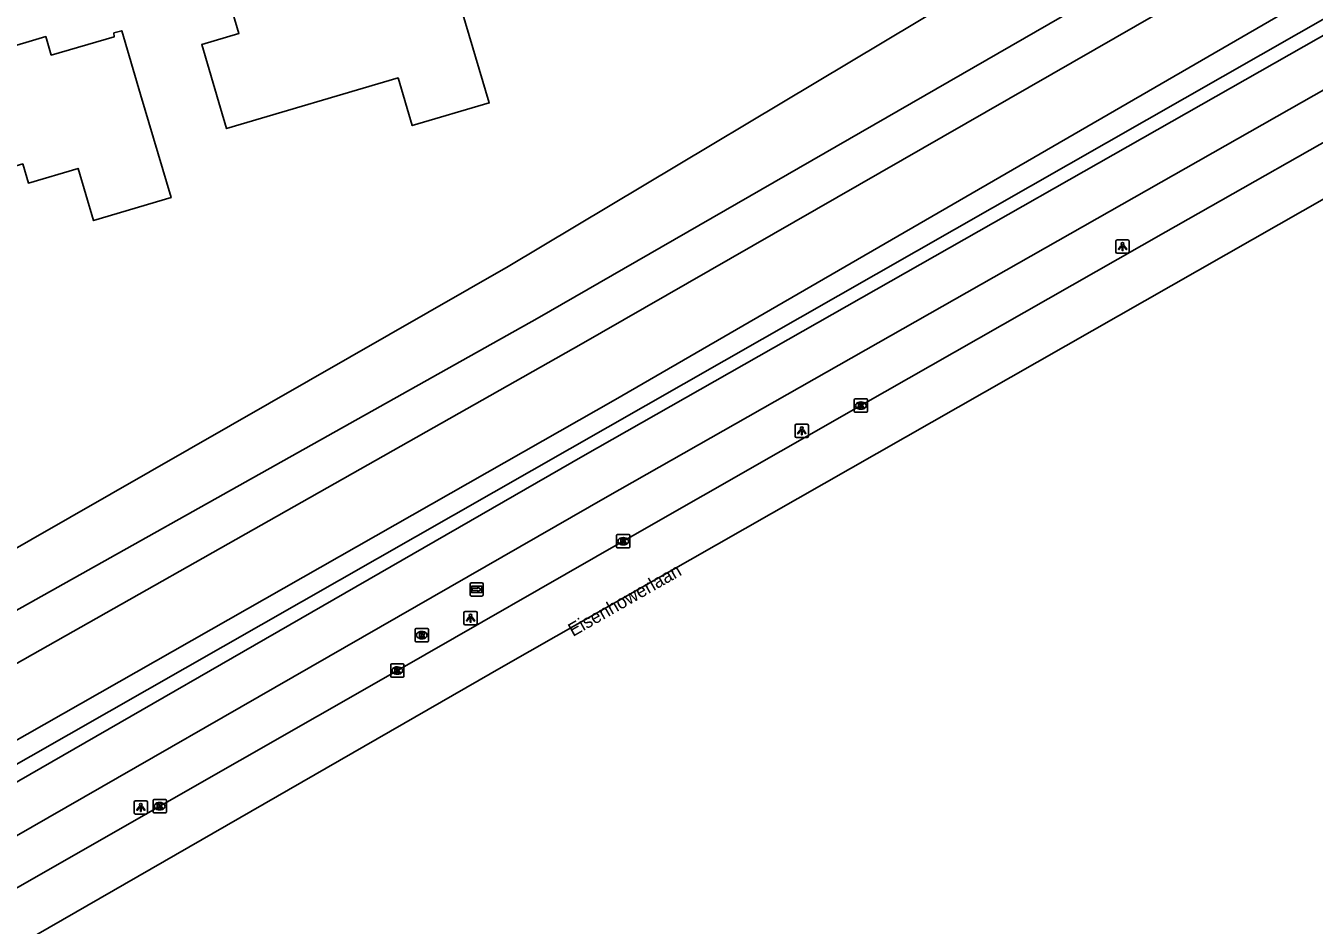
# Model space of a CAD drawing. Extents: x 162417 to 163721, y 384268 to 385416.
# Drawn here: x 163373.9 to 163470.9, y 384526.5 to 384594.2 of the extents above; entities that cross this region are included whole.
import ezdxf

# ---------------------------------------------------------------- set-up
doc = ezdxf.new("R2010")
doc.units = 0
for name, color, linetype in [('IMGEO_Fietspad_gesloten', 7, 'Continuous'), ('IMGEO_Groenvoorziening', 7, 'Continuous'), ('IMGEO_Hek', 7, 'Continuous'), ('IMGEO_Kolk', 7, 'Continuous'), ('IMGEO_Lichtpunt', 7, 'Continuous'), ('IMGEO_Openbare_ruimte_label', 7, 'Continuous'), ('IMGEO_Pand', 7, 'Continuous'), ('IMGEO_Rijbaan_regionaal_gesloten', 7, 'Continuous'), ('IMGEO_Rioolput', 7, 'Continuous'), ('IMGEO_Wegwijzer', 7, 'Continuous')]:
    doc.layers.add(name, color=color, linetype=linetype)

msp = doc.modelspace()

# ---------------------------------------------------------------- linework, layer by layer
at = {"layer": 'IMGEO_Fietspad_gesloten'}
for points in [[(163563.615, 384641.938), (163546.208, 384631.66), (163524.745, 384619.501), (163513.726, 384613.258), (163500, 384605.489), (163486.444, 384597.816), (163417.722, 384558.756), (163354.577, 384522.522), (163336.983, 384512.304), (163315.799, 384500), (163237.627, 384454.426), (163127.281, 384389.626), (163118.59, 384384.62), (163112.281, 384381.199), (163106.553, 384378.4)], [(163511.147, 384615.916), (163500, 384609.604), (163484.5, 384600.835), (163415.868, 384561.799), (163356.283, 384527.511), (163355.13, 384526.85)]]:
    msp.add_lwpolyline(points, dxfattribs=at)
at = {"layer": 'IMGEO_Groenvoorziening'}
for points in [[(163490.386, 384642.261), (163488.848, 384640.395), (163492.655, 384633.034), (163494.178, 384625.448), (163477.053, 384616.061), (163410.245, 384576.085), (163356.302, 384545.212), (163353.612, 384549.684), (163345.242, 384548.875)], [(163497.843, 384621.571), (163489.45, 384616.524), (163412.421, 384572.167), (163356.605, 384540.896), (163352.187, 384546.648), (163350.391, 384546.23), (163353.961, 384535.291), (163415.728, 384570.225), (163496.132, 384616.406), (163500, 384619.404), (163501.9, 384620.876)], [(163508.242, 384618.879), (163507.381, 384617.632), (163500, 384613.359), (163418.315, 384566.067), (163354.498, 384529.757)], [(163510.332, 384616.812), (163354.09, 384527.692), (163351.378, 384528.626), (163350.849, 384530.373)]]:
    msp.add_lwpolyline(points, dxfattribs=at)
at = {"layer": 'IMGEO_Hek'}
msp.add_lwpolyline([(163510.332, 384616.812), (163354.09, 384527.692), (163351.378, 384528.626), (163350.849, 384530.373)], dxfattribs=at)
at = {"layer": 'IMGEO_Kolk'}
for p, q in [((163436.298, 384565.181), (163436.298, 384566.033)), ((163436.373, 384566.107), (163437.225, 384566.107)), ((163436.786, 384565.887), (163436.811, 384565.887)), ((163437.299, 384566.033), (163437.299, 384565.181)), ((163437.225, 384565.107), (163436.373, 384565.107)), ((163436.809, 384565.327), (163436.784, 384565.327)), ((163418.404, 384554.965), (163418.404, 384555.817)), ((163418.479, 384555.891), (163419.331, 384555.891)), ((163418.892, 384555.671), (163418.917, 384555.671)), ((163419.405, 384555.817), (163419.405, 384554.965)), ((163419.331, 384554.891), (163418.479, 384554.891)), ((163418.915, 384555.111), (163418.89, 384555.111)), ((163401.395, 384545.226), (163401.395, 384546.078)), ((163401.47, 384546.152), (163402.322, 384546.152)), ((163401.883, 384545.932), (163401.908, 384545.932)), ((163402.396, 384546.078), (163402.396, 384545.226)), ((163402.322, 384545.152), (163401.47, 384545.152)), ((163401.906, 384545.372), (163401.881, 384545.372)), ((163383.505, 384535.012), (163383.505, 384535.864)), ((163383.58, 384535.938), (163384.432, 384535.938)), ((163384.506, 384535.864), (163384.506, 384535.012)), ((163384.432, 384534.938), (163383.58, 384534.938)), ((163384.016, 384535.158), (163383.991, 384535.158)), ((163383.993, 384535.718), (163384.018, 384535.718))]:
    msp.add_line(p, q, dxfattribs=at)
for points in [[(163436.298, 384565.181), (163436.298, 384566.033)], [(163436.373, 384566.107), (163437.225, 384566.107)], [(163436.619, 384565.807), (163436.742, 384565.807), (163436.742, 384565.656), (163436.872, 384565.807), (163437.036, 384565.807), (163436.89, 384565.656), (163437.043, 384565.407), (163436.891, 384565.407), (163436.806, 384565.571), (163436.742, 384565.504), (163436.742, 384565.407), (163436.619, 384565.407), (163436.619, 384565.807)], [(163437.299, 384566.033), (163437.299, 384565.181)], [(163437.225, 384565.107), (163436.373, 384565.107)], [(163418.404, 384554.965), (163418.404, 384555.817)], [(163418.479, 384555.891), (163419.331, 384555.891)], [(163418.725, 384555.591), (163418.848, 384555.591), (163418.848, 384555.44), (163418.978, 384555.591), (163419.142, 384555.591), (163418.996, 384555.44), (163419.149, 384555.191), (163418.997, 384555.191), (163418.912, 384555.355), (163418.848, 384555.288), (163418.848, 384555.191), (163418.725, 384555.191), (163418.725, 384555.591)], [(163419.405, 384555.817), (163419.405, 384554.965)], [(163419.331, 384554.891), (163418.479, 384554.891)], [(163401.395, 384545.226), (163401.395, 384546.078)], [(163401.47, 384546.152), (163402.322, 384546.152)], [(163401.716, 384545.852), (163401.839, 384545.852), (163401.839, 384545.701), (163401.969, 384545.852), (163402.133, 384545.852), (163401.987, 384545.701), (163402.14, 384545.452), (163401.988, 384545.452), (163401.903, 384545.616), (163401.839, 384545.549), (163401.839, 384545.452), (163401.716, 384545.452), (163401.716, 384545.852)], [(163402.396, 384546.078), (163402.396, 384545.226)], [(163402.322, 384545.152), (163401.47, 384545.152)], [(163383.505, 384535.012), (163383.505, 384535.864)], [(163383.58, 384535.938), (163384.432, 384535.938)], [(163384.506, 384535.864), (163384.506, 384535.012)], [(163384.432, 384534.938), (163383.58, 384534.938)], [(163383.826, 384535.638), (163383.949, 384535.638), (163383.949, 384535.487), (163384.079, 384535.638), (163384.243, 384535.638), (163384.097, 384535.487), (163384.25, 384535.238), (163384.098, 384535.238), (163384.013, 384535.402), (163383.949, 384535.335), (163383.949, 384535.238), (163383.826, 384535.238), (163383.826, 384535.638)]]:
    msp.add_lwpolyline(points, dxfattribs=at)
for centre, start, end in [((163436.375, 384566.031), 91.55205, 178.44795), ((163436.375, 384566.031), 91.55205, 178.44795), ((163437.223, 384566.031), 1.55205, 88.44795), ((163437.223, 384566.031), 1.55205, 88.44795), ((163436.375, 384565.183), 181.55205, 268.44795), ((163436.375, 384565.183), 181.55205, 268.44795), ((163437.223, 384565.183), 271.55205, 358.44795), ((163437.223, 384565.183), 271.55205, 358.44795), ((163418.481, 384555.815), 91.55205, 178.44795), ((163418.481, 384555.815), 91.55205, 178.44795), ((163419.329, 384555.815), 1.55205, 88.44795), ((163419.329, 384555.815), 1.55205, 88.44795), ((163418.481, 384554.967), 181.55205, 268.44795), ((163418.481, 384554.967), 181.55205, 268.44795), ((163419.329, 384554.967), 271.55205, 358.44795), ((163419.329, 384554.967), 271.55205, 358.44795), ((163401.472, 384546.076), 91.55205, 178.44795), ((163401.472, 384546.076), 91.55205, 178.44795), ((163402.32, 384546.076), 1.55205, 88.44795), ((163402.32, 384546.076), 1.55205, 88.44795), ((163401.472, 384545.228), 181.55205, 268.44795), ((163401.472, 384545.228), 181.55205, 268.44795), ((163402.32, 384545.228), 271.55205, 358.44795), ((163402.32, 384545.228), 271.55205, 358.44795), ((163383.582, 384535.862), 91.55205, 178.44795), ((163383.582, 384535.862), 91.55205, 178.44795), ((163384.43, 384535.862), 1.55205, 88.44795), ((163384.43, 384535.862), 1.55205, 88.44795), ((163383.582, 384535.014), 181.55205, 268.44795), ((163383.582, 384535.014), 181.55205, 268.44795), ((163384.43, 384535.014), 271.55205, 358.44795), ((163384.43, 384535.014), 271.55205, 358.44795)]:
    msp.add_arc(centre, 0.0765, start, end, dxfattribs=at)
for centre, major_axis, ratio, start_param, end_param in [((163436.785, 384565.607), (-0.387, 0.002), 0.722429, 4.712389, 7.853982), ((163436.81, 384565.607), (-0.39, 0.002), 0.717154, 1.570796, 4.712389), ((163418.891, 384555.391), (-0.387, 0.002), 0.722429, 4.712389, 7.853982), ((163418.916, 384555.391), (-0.39, 0.002), 0.717154, 1.570796, 4.712389), ((163401.882, 384545.652), (-0.387, 0.002), 0.722429, 4.712389, 7.853982), ((163401.907, 384545.652), (-0.39, 0.002), 0.717154, 1.570796, 4.712389), ((163383.992, 384535.438), (-0.387, 0.002), 0.722429, 4.712389, 7.853982), ((163384.017, 384535.438), (-0.39, 0.002), 0.717154, 1.570796, 4.712389)]:
    msp.add_ellipse(centre, major_axis=major_axis, ratio=ratio, start_param=start_param, end_param=end_param, dxfattribs=at)
at = {"layer": 'IMGEO_Lichtpunt'}
for p, q in [((163455.994, 384577.985), (163455.994, 384577.178)), ((163455.994, 384577.985), (163455.994, 384577.178)), ((163456.896, 384578.08), (163456.088, 384578.08)), ((163456.896, 384578.08), (163456.088, 384578.08)), ((163456.99, 384577.178), (163456.99, 384577.985)), ((163456.99, 384577.178), (163456.99, 384577.985)), ((163456.088, 384577.084), (163456.896, 384577.084)), ((163456.088, 384577.084), (163456.896, 384577.084)), ((163431.841, 384564.114), (163431.841, 384563.307)), ((163431.841, 384564.114), (163431.841, 384563.307)), ((163432.743, 384564.209), (163431.935, 384564.209)), ((163432.743, 384564.209), (163431.935, 384564.209)), ((163432.837, 384563.307), (163432.837, 384564.114)), ((163432.837, 384563.307), (163432.837, 384564.114)), ((163431.935, 384563.213), (163432.743, 384563.213)), ((163431.935, 384563.213), (163432.743, 384563.213)), ((163406.912, 384550.003), (163406.912, 384549.196)), ((163406.912, 384550.003), (163406.912, 384549.196)), ((163407.814, 384550.098), (163407.006, 384550.098)), ((163407.814, 384550.098), (163407.006, 384550.098)), ((163407.908, 384549.196), (163407.908, 384550.003)), ((163407.908, 384549.196), (163407.908, 384550.003)), ((163407.006, 384549.102), (163407.814, 384549.102)), ((163407.006, 384549.102), (163407.814, 384549.102)), ((163382.085, 384535.753), (163382.085, 384534.946)), ((163382.085, 384535.753), (163382.085, 384534.946)), ((163382.987, 384535.848), (163382.179, 384535.848)), ((163382.987, 384535.848), (163382.179, 384535.848)), ((163383.081, 384534.946), (163383.081, 384535.753)), ((163383.081, 384534.946), (163383.081, 384535.753)), ((163382.179, 384534.852), (163382.987, 384534.852)), ((163382.179, 384534.852), (163382.987, 384534.852))]:
    msp.add_line(p, q, dxfattribs=at)
for points in [[(163456.368, 384577.649), (163456.407, 384577.621), (163456.219, 384577.359), (163456.181, 384577.386), (163456.368, 384577.649)], [(163456.47, 384577.601), (163456.517, 384577.601), (163456.517, 384577.279), (163456.47, 384577.279), (163456.47, 384577.601)], [(163456.58, 384577.621), (163456.618, 384577.648), (163456.805, 384577.386), (163456.766, 384577.358), (163456.58, 384577.621)], [(163432.215, 384563.778), (163432.254, 384563.75), (163432.066, 384563.488), (163432.028, 384563.515), (163432.215, 384563.778)], [(163432.317, 384563.73), (163432.364, 384563.73), (163432.364, 384563.408), (163432.317, 384563.408), (163432.317, 384563.73)], [(163432.427, 384563.75), (163432.465, 384563.777), (163432.652, 384563.515), (163432.613, 384563.487), (163432.427, 384563.75)], [(163407.286, 384549.667), (163407.325, 384549.639), (163407.137, 384549.377), (163407.099, 384549.404), (163407.286, 384549.667)], [(163407.388, 384549.619), (163407.435, 384549.619), (163407.435, 384549.297), (163407.388, 384549.297), (163407.388, 384549.619)], [(163407.498, 384549.639), (163407.536, 384549.666), (163407.723, 384549.404), (163407.684, 384549.376), (163407.498, 384549.639)], [(163382.459, 384535.417), (163382.498, 384535.389), (163382.31, 384535.127), (163382.272, 384535.154), (163382.459, 384535.417)], [(163382.561, 384535.369), (163382.608, 384535.369), (163382.608, 384535.047), (163382.561, 384535.047), (163382.561, 384535.369)], [(163382.671, 384535.389), (163382.709, 384535.416), (163382.896, 384535.154), (163382.857, 384535.126), (163382.671, 384535.389)]]:
    msp.add_lwpolyline(points, dxfattribs=at)
for centre in [(163456.493, 384577.783), (163432.34, 384563.912), (163407.411, 384549.801), (163382.584, 384535.551)]:
    msp.add_circle(centre, 0.0994, dxfattribs=at)
for centre, start, end in [((163456.088, 384577.985), 90, 180), ((163456.088, 384577.985), 90, 180), ((163456.896, 384577.985), 0, 90), ((163456.896, 384577.985), 0, 90), ((163456.088, 384577.178), 180, 270), ((163456.088, 384577.178), 180, 270), ((163456.896, 384577.178), 270, 0), ((163456.896, 384577.178), 270, 360), ((163431.935, 384564.114), 90, 180), ((163431.935, 384564.114), 90, 180), ((163432.743, 384564.114), 0, 90), ((163432.743, 384564.114), 0, 90), ((163431.935, 384563.307), 180, 270), ((163431.935, 384563.307), 180, 270), ((163432.743, 384563.307), 270, 0), ((163432.743, 384563.307), 270, 360), ((163407.006, 384550.003), 90, 180), ((163407.006, 384550.003), 90, 180), ((163407.814, 384550.003), 0, 90), ((163407.814, 384550.003), 0, 90), ((163407.006, 384549.196), 180, 270), ((163407.006, 384549.196), 180, 270), ((163407.814, 384549.196), 270, 0), ((163407.814, 384549.196), 270, 360), ((163382.179, 384535.753), 90, 180), ((163382.179, 384535.753), 90, 180), ((163382.987, 384535.753), 0, 90), ((163382.987, 384535.753), 0, 90), ((163382.179, 384534.946), 180, 270), ((163382.179, 384534.946), 180, 270), ((163382.987, 384534.946), 270, 0), ((163382.987, 384534.946), 270, 360)]:
    msp.add_arc(centre, 0.0946, start, end, dxfattribs=at)
at = {"layer": 'IMGEO_Pand'}
for points in [[(163388.86, 384597.387), (163389.971, 384593.627), (163387.17, 384592.799), (163388.587, 384588.004), (163389.04, 384586.469), (163401.957, 384590.287), (163403.019, 384586.69), (163408.811, 384588.401), (163405.052, 384601.119), (163403.635, 384605.913), (163397.853, 384604.204), (163398.987, 384600.369), (163392.697, 384598.51)], [(163365.825, 384590.479), (163364.706, 384590.192), (163360.682, 384589.023), (163362.106, 384584.231), (163363.586, 384579.248), (163364.755, 384575.318), (163371.456, 384577.31), (163370.27, 384581.226), (163369.845, 384582.664), (163373.698, 384583.805), (163374.124, 384582.367), (163377.865, 384583.474), (163379.028, 384579.543), (163384.859, 384581.269), (163382.561, 384589.036), (163381.143, 384593.83), (163380.557, 384593.672), (163380.59, 384593.387), (163375.844, 384591.998), (163375.427, 384593.399), (163368.54, 384591.356), (163369.07, 384589.543), (163367.915, 384589.188), (163367.599, 384590.132)]]:
    msp.add_lwpolyline(points, dxfattribs=at)
at = {"layer": 'IMGEO_Rijbaan_regionaal_gesloten'}
for points in [[(163698.754, 384708.845), (163688.73, 384703.305), (163649.638, 384681.228), (163618.533, 384663.566), (163596.045, 384651.581), (163528.5, 384613.585), (163468.247, 384579.241), (163409.885, 384545.975), (163340.634, 384506.16), (163340.62, 384506.152), (163245.344, 384450.732), (163192.965, 384420.029), (163150.615, 384395.072), (163132.36, 384384.338), (163123.086, 384378.886)], [(163159.702, 384404.658), (163177.428, 384415.092), (163194.296, 384425.014), (163209.47, 384433.918), (163228.943, 384445.358), (163245.842, 384455.282), (163261.887, 384464.663), (163280.528, 384475.539), (163295.714, 384484.368), (163315.265, 384495.759), (163322.552, 384500), (163332.188, 384505.608), (163338.716, 384509.388), (163350.031, 384515.939), (163367.013, 384525.722), (163384.007, 384535.437), (163401.897, 384545.651), (163418.907, 384555.39), (163436.8, 384565.606), (163459.744, 384578.685), (163476.382, 384588.124)]]:
    msp.add_lwpolyline(points, dxfattribs=at)
at = {"layer": 'IMGEO_Rioolput'}
for p, q in [((163403.237, 384547.898), (163403.237, 384548.75)), ((163403.312, 384548.824), (163404.164, 384548.824)), ((163403.725, 384548.604), (163403.75, 384548.604)), ((163404.238, 384548.75), (163404.238, 384547.898)), ((163404.164, 384547.824), (163403.312, 384547.824)), ((163403.748, 384548.044), (163403.723, 384548.044))]:
    msp.add_line(p, q, dxfattribs=at)
for points in [[(163403.237, 384547.898), (163403.237, 384548.75)], [(163403.312, 384548.824), (163404.164, 384548.824)], [(163403.826, 384548.522), (163403.574, 384548.524), (163403.574, 384548.124)], [(163403.752, 384548.443), (163403.698, 384548.443), (163403.698, 384548.362)], [(163403.698, 384548.362), (163403.75, 384548.362)], [(163404.238, 384548.75), (163404.238, 384547.898)], [(163404.164, 384547.824), (163403.312, 384547.824)], [(163403.574, 384548.124), (163403.698, 384548.124), (163403.698, 384548.286), (163403.709, 384548.286)], [(163403.756, 384548.257), (163403.827, 384548.124), (163403.967, 384548.124), (163403.902, 384548.25)]]:
    msp.add_lwpolyline(points, dxfattribs=at)
for centre, radius, start, end in [((163403.314, 384548.748), 0.0765, 91.55205, 178.44795), ((163403.314, 384548.748), 0.0765, 91.55205, 178.44795), ((163403.734, 384548.551), 0.19, 274.7715, 282.96867), ((163403.758, 384548.347), 0.0964, 77.00612, 93.18647), ((163403.772, 384548.404), 0.0378, 276.66336, 79.67722), ((163403.825, 384548.412), 0.109, 350.36119, 89.41601), ((163403.823, 384548.412), 0.112, 277.58423, 350.98172), ((163404.162, 384548.748), 0.0765, 1.55205, 88.44795), ((163404.162, 384548.748), 0.0765, 1.55205, 88.44795), ((163403.314, 384547.9), 0.0765, 181.55205, 268.44795), ((163403.314, 384547.9), 0.0765, 181.55205, 268.44795), ((163403.708, 384548.233), 0.0533, 26.02933, 88.69889), ((163403.807, 384548.197), 0.108, 29.51342, 73.79051), ((163404.162, 384547.9), 0.0765, 271.55205, 358.44795), ((163404.162, 384547.9), 0.0765, 271.55205, 358.44795)]:
    msp.add_arc(centre, radius, start, end, dxfattribs=at)
for centre, major_axis, ratio, start_param, end_param in [((163403.724, 384548.324), (-0.387, 0.002), 0.722429, 4.712389, 7.853982), ((163403.749, 384548.324), (-0.39, 0.002), 0.717154, 1.570796, 4.712389)]:
    msp.add_ellipse(centre, major_axis=major_axis, ratio=ratio, start_param=start_param, end_param=end_param, dxfattribs=at)
at = {"layer": 'IMGEO_Wegwijzer'}
for p, q in [((163407.472, 384552.267), (163408.262, 384552.267)), ((163408.262, 384552.267), (163407.472, 384552.267)), ((163407.372, 384551.367), (163407.372, 384552.167)), ((163407.372, 384552.167), (163407.372, 384551.367)), ((163408.262, 384551.267), (163407.472, 384551.267)), ((163407.472, 384551.267), (163408.262, 384551.267)), ((163408.362, 384552.167), (163408.362, 384551.367)), ((163408.362, 384551.367), (163408.362, 384552.167))]:
    msp.add_line(p, q, dxfattribs=at)
for points in [[(163407.473, 384551.999), (163408.261, 384551.999), (163408.261, 384551.535), (163407.473, 384551.535), (163407.473, 384551.999)], [(163407.538, 384551.851), (163407.538, 384551.767), (163407.538, 384551.683), (163407.949, 384551.683), (163407.949, 384551.6), (163408.196, 384551.767), (163407.949, 384551.934), (163407.949, 384551.851), (163407.538, 384551.851)]]:
    msp.add_lwpolyline(points, dxfattribs=at)
for centre, start, end in [((163407.472, 384552.167), 90, 180), ((163407.472, 384552.167), 90, 180), ((163408.262, 384552.167), 0, 90), ((163408.262, 384552.167), 360, 90), ((163407.472, 384551.367), 180, 270), ((163407.472, 384551.367), 180, 270), ((163408.262, 384551.367), 270, 0), ((163408.262, 384551.367), 270, 0)]:
    msp.add_arc(centre, 0.1, start, end, dxfattribs=at)

# ---------------------------------------------------------------- texts
at = {"layer": 'IMGEO_Openbare_ruimte_label'}
msp.add_text('Eisenhowerlaan', height=1, rotation=29.66672, dxfattribs=at).set_placement((163415.118, 384548.18))

doc.saveas('drawing.dxf')
